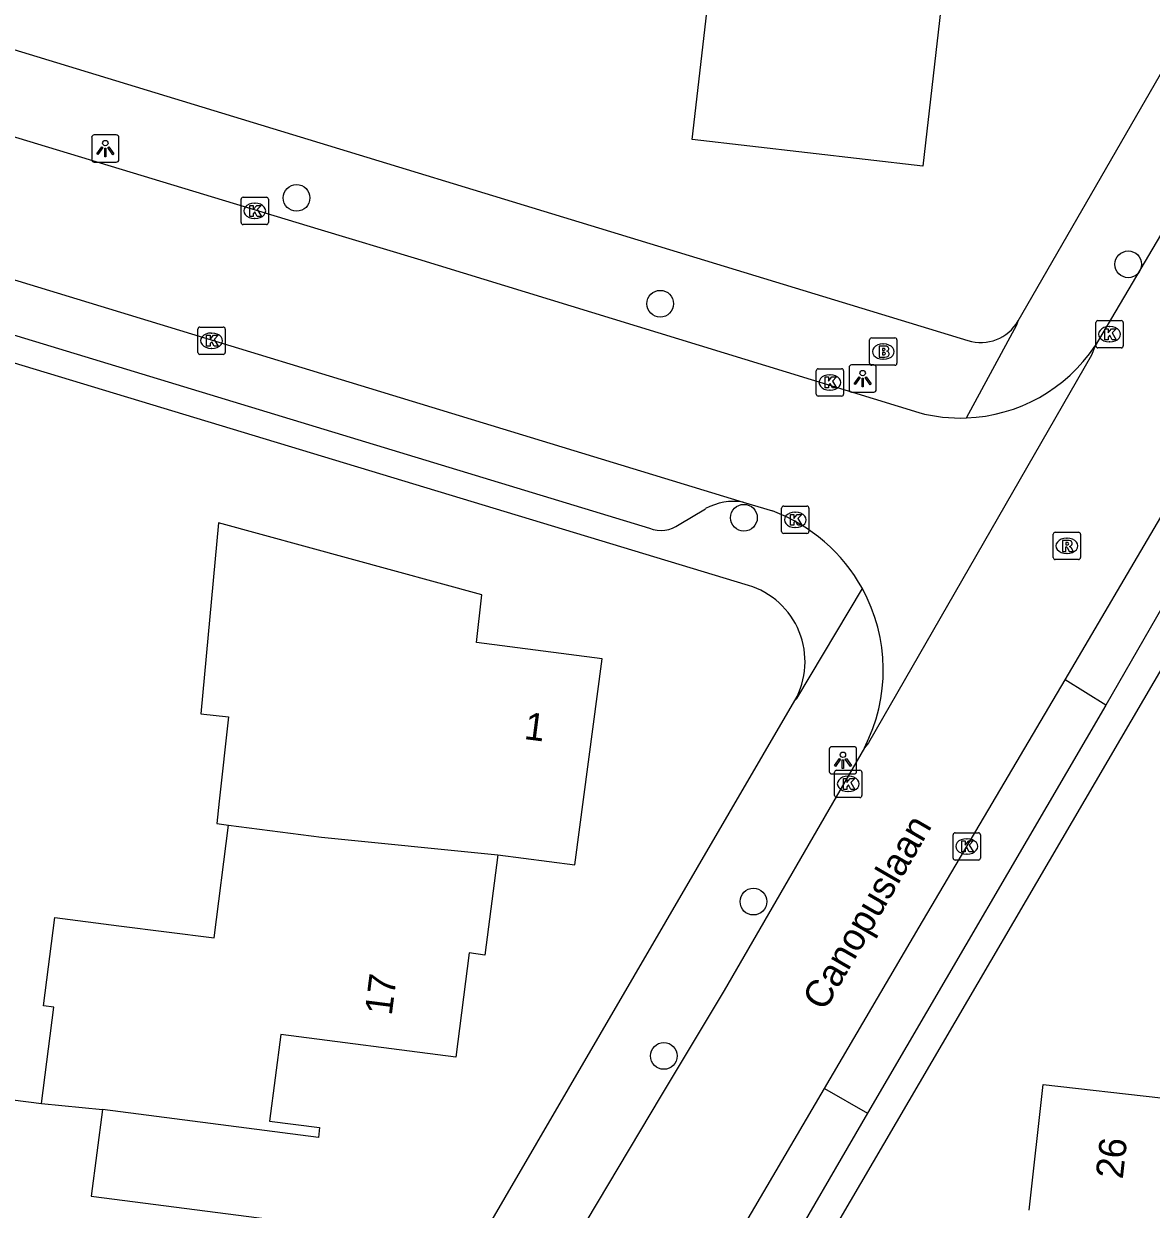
# Model space of a CAD drawing. Extents: x 162398 to 163643, y 386453 to 387397.
# Drawn here: x 162852.66 to 162893.95, y 386684.22 to 386727.63 of the extents above; entities that cross this region are included whole.
import ezdxf

# ---------------------------------------------------------------- set-up
doc = ezdxf.new("R2010")
doc.units = 0
for name, color, linetype in [('IMGEO_Boom', 7, 'Continuous'), ('IMGEO_Brandkraan', 7, 'Continuous'), ('IMGEO_Kolk', 7, 'Continuous'), ('IMGEO_Lichtpunt', 7, 'Continuous'), ('IMGEO_Openbare_ruimte_label', 7, 'Continuous'), ('IMGEO_Pand', 7, 'Continuous'), ('IMGEO_Pand_nummerreeks', 7, 'Continuous'), ('IMGEO_Rijbaan_lokaal_open', 7, 'Continuous'), ('IMGEO_Rioolput', 7, 'Continuous'), ('IMGEO_Voetpad_open', 7, 'Continuous')]:
    doc.layers.add(name, color=color, linetype=linetype)

msp = doc.modelspace()

# ---------------------------------------------------------------- linework, layer by layer
at = {"layer": 'IMGEO_Boom'}
for centre in [(162862.649, 386721.249), (162893.101, 386718.817), (162875.964, 386717.375), (162879.029, 386709.541), (162879.377, 386695.487), (162876.097, 386689.837)]:
    msp.add_circle(centre, 0.489, dxfattribs=at)
at = {"layer": 'IMGEO_Brandkraan'}
for p, q in [((162883.632, 386715.196), (162883.632, 386716.048)), ((162883.707, 386716.122), (162884.559, 386716.122)), ((162884.633, 386716.048), (162884.633, 386715.196)), ((162884.12, 386715.902), (162884.145, 386715.902)), ((162884.143, 386715.342), (162884.118, 386715.342)), ((162884.559, 386715.122), (162883.707, 386715.122))]:
    msp.add_line(p, q, dxfattribs=at)
for points in [[(162883.632, 386715.196), (162883.632, 386716.048)], [(162883.707, 386716.122), (162884.559, 386716.122)], [(162884.633, 386716.048), (162884.633, 386715.196)], [(162883.98, 386715.822), (162883.98, 386715.422), (162884.193, 386715.422)], [(162884.211, 386715.822), (162883.98, 386715.822)], [(162884.159, 386715.741), (162884.105, 386715.741), (162884.105, 386715.665)], [(162884.105, 386715.665), (162884.158, 386715.665)], [(162884.167, 386715.589), (162884.105, 386715.589), (162884.105, 386715.508)], [(162884.105, 386715.508), (162884.167, 386715.508)], [(162884.559, 386715.122), (162883.707, 386715.122)]]:
    msp.add_lwpolyline(points, dxfattribs=at)
for centre, radius, start, end in [((162883.709, 386716.046), 0.0765, 91.552, 178.448), ((162883.709, 386716.046), 0.0765, 91.552, 178.448), ((162884.557, 386716.046), 0.0765, 1.552, 88.448), ((162884.557, 386716.046), 0.0765, 1.552, 88.448), ((162884.16, 386715.703), 0.0379, 267.8285, 90.9355), ((162884.215, 386715.677), 0.145, 59.4692, 91.5367), ((162884.24, 386715.724), 0.0922, 285.5137, 58.1501), ((162884.245, 386715.532), 0.105, 301.3115, 78.989), ((162883.709, 386715.198), 0.0765, 181.552, 268.448), ((162883.709, 386715.198), 0.0765, 181.552, 268.448), ((162884.168, 386715.548), 0.0404, 269.8759, 90.5077), ((162884.199, 386715.673), 0.251, 268.6676, 293.5347), ((162884.557, 386715.198), 0.0765, 271.552, 358.448), ((162884.557, 386715.198), 0.0765, 271.552, 358.448)]:
    msp.add_arc(centre, radius, start, end, dxfattribs=at)
for centre, major_axis, ratio, start_param, end_param in [((162884.119, 386715.622), (-0.387, 0.002), 0.722429, 4.712389, 7.853982), ((162884.144, 386715.622), (-0.39, 0.002), 0.717154, 1.570796, 4.712389)]:
    msp.add_ellipse(centre, major_axis=major_axis, ratio=ratio, start_param=start_param, end_param=end_param, dxfattribs=at)
at = {"layer": 'IMGEO_Kolk'}
for p, q in [((162860.691, 386721.273), (162861.543, 386721.273)), ((162860.616, 386720.347), (162860.616, 386721.199)), ((162861.104, 386721.053), (162861.129, 386721.053)), ((162861.617, 386721.199), (162861.617, 386720.347)), ((162861.127, 386720.493), (162861.102, 386720.493)), ((162861.543, 386720.273), (162860.691, 386720.273)), ((162859.111, 386716.521), (162859.963, 386716.521)), ((162891.917, 386715.831), (162891.917, 386716.683)), ((162891.992, 386716.757), (162892.844, 386716.757)), ((162892.405, 386716.537), (162892.43, 386716.537)), ((162892.918, 386716.683), (162892.918, 386715.831)), ((162859.036, 386715.595), (162859.036, 386716.447)), ((162859.524, 386716.301), (162859.549, 386716.301)), ((162860.037, 386716.447), (162860.037, 386715.595)), ((162859.547, 386715.741), (162859.522, 386715.741)), ((162892.844, 386715.757), (162891.992, 386715.757)), ((162892.428, 386715.977), (162892.403, 386715.977)), ((162859.963, 386715.521), (162859.111, 386715.521)), ((162881.678, 386714.067), (162881.678, 386714.919)), ((162881.753, 386714.993), (162882.605, 386714.993)), ((162882.166, 386714.773), (162882.191, 386714.773)), ((162882.679, 386714.919), (162882.679, 386714.067)), ((162882.605, 386713.993), (162881.753, 386713.993)), ((162882.189, 386714.213), (162882.164, 386714.213)), ((162880.485, 386709.964), (162881.337, 386709.964)), ((162880.41, 386709.038), (162880.41, 386709.89)), ((162880.898, 386709.744), (162880.923, 386709.744)), ((162881.411, 386709.89), (162881.411, 386709.038)), ((162880.921, 386709.184), (162880.896, 386709.184)), ((162881.337, 386708.964), (162880.485, 386708.964)), ((162882.349, 386699.371), (162882.349, 386700.223)), ((162882.424, 386700.297), (162883.276, 386700.297)), ((162882.837, 386700.077), (162882.862, 386700.077)), ((162883.35, 386700.223), (162883.35, 386699.371)), ((162883.276, 386699.297), (162882.424, 386699.297)), ((162882.86, 386699.517), (162882.835, 386699.517)), ((162886.689, 386697.082), (162886.689, 386697.934)), ((162886.764, 386698.008), (162887.616, 386698.008)), ((162887.69, 386697.934), (162887.69, 386697.082)), ((162887.177, 386697.788), (162887.202, 386697.788)), ((162887.616, 386697.008), (162886.764, 386697.008)), ((162887.2, 386697.228), (162887.175, 386697.228))]:
    msp.add_line(p, q, dxfattribs=at)
for points in [[(162860.691, 386721.273), (162861.543, 386721.273)], [(162860.616, 386720.347), (162860.616, 386721.199)], [(162860.937, 386720.973), (162861.06, 386720.973), (162861.06, 386720.822), (162861.19, 386720.973), (162861.354, 386720.973), (162861.208, 386720.822), (162861.361, 386720.573), (162861.209, 386720.573), (162861.124, 386720.737), (162861.06, 386720.67), (162861.06, 386720.573), (162860.937, 386720.573), (162860.937, 386720.973)], [(162861.617, 386721.199), (162861.617, 386720.347)], [(162861.543, 386720.273), (162860.691, 386720.273)], [(162859.111, 386716.521), (162859.963, 386716.521)], [(162891.917, 386715.831), (162891.917, 386716.683)], [(162891.992, 386716.757), (162892.844, 386716.757)], [(162892.918, 386716.683), (162892.918, 386715.831)], [(162859.036, 386715.595), (162859.036, 386716.447)], [(162859.357, 386716.221), (162859.48, 386716.221), (162859.48, 386716.07), (162859.61, 386716.221), (162859.774, 386716.221), (162859.628, 386716.07), (162859.781, 386715.821), (162859.629, 386715.821), (162859.544, 386715.985), (162859.48, 386715.918), (162859.48, 386715.821), (162859.357, 386715.821), (162859.357, 386716.221)], [(162860.037, 386716.447), (162860.037, 386715.595)], [(162892.238, 386716.457), (162892.361, 386716.457), (162892.361, 386716.306), (162892.491, 386716.457), (162892.655, 386716.457), (162892.509, 386716.306), (162892.662, 386716.057), (162892.51, 386716.057), (162892.425, 386716.221), (162892.361, 386716.154), (162892.361, 386716.057), (162892.238, 386716.057), (162892.238, 386716.457)], [(162892.844, 386715.757), (162891.992, 386715.757)], [(162859.963, 386715.521), (162859.111, 386715.521)], [(162881.678, 386714.067), (162881.678, 386714.919)], [(162881.753, 386714.993), (162882.605, 386714.993)], [(162882.679, 386714.919), (162882.679, 386714.067)], [(162881.999, 386714.693), (162882.122, 386714.693), (162882.122, 386714.542), (162882.252, 386714.693), (162882.416, 386714.693), (162882.27, 386714.542), (162882.423, 386714.293), (162882.271, 386714.293), (162882.186, 386714.457), (162882.122, 386714.39), (162882.122, 386714.293), (162881.999, 386714.293), (162881.999, 386714.693)], [(162882.605, 386713.993), (162881.753, 386713.993)], [(162880.485, 386709.964), (162881.337, 386709.964)], [(162880.41, 386709.038), (162880.41, 386709.89)], [(162880.731, 386709.664), (162880.854, 386709.664), (162880.854, 386709.513), (162880.984, 386709.664), (162881.148, 386709.664), (162881.002, 386709.513), (162881.155, 386709.264), (162881.003, 386709.264), (162880.918, 386709.428), (162880.854, 386709.361), (162880.854, 386709.264), (162880.731, 386709.264), (162880.731, 386709.664)], [(162881.411, 386709.89), (162881.411, 386709.038)], [(162881.337, 386708.964), (162880.485, 386708.964)], [(162882.349, 386699.371), (162882.349, 386700.223)], [(162882.424, 386700.297), (162883.276, 386700.297)], [(162882.67, 386699.997), (162882.793, 386699.997), (162882.793, 386699.846), (162882.923, 386699.997), (162883.087, 386699.997), (162882.941, 386699.846), (162883.094, 386699.597), (162882.942, 386699.597), (162882.857, 386699.761), (162882.793, 386699.694), (162882.793, 386699.597), (162882.67, 386699.597), (162882.67, 386699.997)], [(162883.35, 386700.223), (162883.35, 386699.371)], [(162883.276, 386699.297), (162882.424, 386699.297)], [(162886.689, 386697.082), (162886.689, 386697.934)], [(162886.764, 386698.008), (162887.616, 386698.008)], [(162887.69, 386697.934), (162887.69, 386697.082)], [(162887.01, 386697.708), (162887.133, 386697.708), (162887.133, 386697.557), (162887.263, 386697.708), (162887.427, 386697.708), (162887.281, 386697.557), (162887.434, 386697.308), (162887.282, 386697.308), (162887.197, 386697.472), (162887.133, 386697.405), (162887.133, 386697.308), (162887.01, 386697.308), (162887.01, 386697.708)], [(162887.616, 386697.008), (162886.764, 386697.008)]]:
    msp.add_lwpolyline(points, dxfattribs=at)
for centre, start, end in [((162860.693, 386721.197), 91.552, 178.448), ((162860.693, 386721.197), 91.552, 178.448), ((162861.541, 386721.197), 1.552, 88.448), ((162861.541, 386721.197), 1.552, 88.448), ((162860.693, 386720.349), 181.552, 268.448), ((162860.693, 386720.349), 181.552, 268.448), ((162861.541, 386720.349), 271.552, 358.448), ((162861.541, 386720.349), 271.552, 358.448), ((162859.113, 386716.445), 91.552, 178.448), ((162859.113, 386716.445), 91.552, 178.448), ((162859.961, 386716.445), 1.552, 88.448), ((162859.961, 386716.445), 1.552, 88.448), ((162891.994, 386716.681), 91.552, 178.448), ((162891.994, 386716.681), 91.552, 178.448), ((162892.842, 386716.681), 1.552, 88.448), ((162892.842, 386716.681), 1.552, 88.448), ((162891.994, 386715.833), 181.552, 268.448), ((162891.994, 386715.833), 181.552, 268.448), ((162892.842, 386715.833), 271.552, 358.448), ((162892.842, 386715.833), 271.552, 358.448), ((162859.113, 386715.597), 181.552, 268.448), ((162859.113, 386715.597), 181.552, 268.448), ((162859.961, 386715.597), 271.552, 358.448), ((162859.961, 386715.597), 271.552, 358.448), ((162881.755, 386714.917), 91.552, 178.448), ((162881.755, 386714.917), 91.552, 178.448), ((162882.603, 386714.917), 1.552, 88.448), ((162882.603, 386714.917), 1.552, 88.448), ((162881.755, 386714.069), 181.552, 268.448), ((162881.755, 386714.069), 181.552, 268.448), ((162882.603, 386714.069), 271.552, 358.448), ((162882.603, 386714.069), 271.552, 358.448), ((162880.487, 386709.888), 91.552, 178.448), ((162880.487, 386709.888), 91.552, 178.448), ((162881.335, 386709.888), 1.552, 88.448), ((162881.335, 386709.888), 1.552, 88.448), ((162880.487, 386709.04), 181.552, 268.448), ((162880.487, 386709.04), 181.552, 268.448), ((162881.335, 386709.04), 271.552, 358.448), ((162881.335, 386709.04), 271.552, 358.448), ((162882.426, 386700.221), 91.552, 178.448), ((162882.426, 386700.221), 91.552, 178.448), ((162883.274, 386700.221), 1.552, 88.448), ((162883.274, 386700.221), 1.552, 88.448), ((162882.426, 386699.373), 181.552, 268.448), ((162882.426, 386699.373), 181.552, 268.448), ((162883.274, 386699.373), 271.552, 358.448), ((162883.274, 386699.373), 271.552, 358.448), ((162886.766, 386697.932), 91.552, 178.448), ((162886.766, 386697.932), 91.552, 178.448), ((162887.614, 386697.932), 1.552, 88.448), ((162887.614, 386697.932), 1.552, 88.448), ((162886.766, 386697.084), 181.552, 268.448), ((162886.766, 386697.084), 181.552, 268.448), ((162887.614, 386697.084), 271.552, 358.448), ((162887.614, 386697.084), 271.552, 358.448)]:
    msp.add_arc(centre, 0.0765, start, end, dxfattribs=at)
for centre, major_axis, ratio, start_param, end_param in [((162861.103, 386720.773), (-0.387, 0.002), 0.722429, 4.712389, 7.853982), ((162861.128, 386720.773), (-0.39, 0.002), 0.717154, 1.570796, 4.712389), ((162892.404, 386716.257), (-0.387, 0.002), 0.722429, 4.712389, 7.853982), ((162892.429, 386716.257), (-0.39, 0.002), 0.717154, 1.570796, 4.712389), ((162859.523, 386716.021), (-0.387, 0.002), 0.722429, 4.712389, 7.853982), ((162859.548, 386716.021), (-0.39, 0.002), 0.717154, 1.570796, 4.712389), ((162882.165, 386714.493), (-0.387, 0.002), 0.722429, 4.712389, 7.853982), ((162882.19, 386714.493), (-0.39, 0.002), 0.717154, 1.570796, 4.712389), ((162880.897, 386709.464), (-0.387, 0.002), 0.722429, 4.712389, 7.853982), ((162880.922, 386709.464), (-0.39, 0.002), 0.717154, 1.570796, 4.712389), ((162882.836, 386699.797), (-0.387, 0.002), 0.722429, 4.712389, 7.853982), ((162882.861, 386699.797), (-0.39, 0.002), 0.717154, 1.570796, 4.712389), ((162887.176, 386697.508), (-0.387, 0.002), 0.722429, 4.712389, 7.853982), ((162887.201, 386697.508), (-0.39, 0.002), 0.717154, 1.570796, 4.712389)]:
    msp.add_ellipse(centre, major_axis=major_axis, ratio=ratio, start_param=start_param, end_param=end_param, dxfattribs=at)
at = {"layer": 'IMGEO_Lichtpunt'}
for p, q in [((162855.147, 386723.458), (162855.147, 386722.651)), ((162855.147, 386723.458), (162855.147, 386722.651)), ((162856.049, 386723.553), (162855.241, 386723.553)), ((162856.049, 386723.553), (162855.241, 386723.553)), ((162856.143, 386722.651), (162856.143, 386723.458)), ((162856.143, 386722.651), (162856.143, 386723.458)), ((162855.241, 386722.557), (162856.049, 386722.557)), ((162855.241, 386722.557), (162856.049, 386722.557)), ((162882.878, 386715.038), (162882.878, 386714.231)), ((162882.878, 386715.038), (162882.878, 386714.231)), ((162883.78, 386715.133), (162882.972, 386715.133)), ((162883.78, 386715.133), (162882.972, 386715.133)), ((162883.874, 386714.231), (162883.874, 386715.038)), ((162883.874, 386714.231), (162883.874, 386715.038)), ((162882.972, 386714.137), (162883.78, 386714.137)), ((162882.972, 386714.137), (162883.78, 386714.137)), ((162882.156, 386701.063), (162882.156, 386700.256)), ((162882.156, 386701.063), (162882.156, 386700.256)), ((162883.058, 386701.158), (162882.25, 386701.158)), ((162883.058, 386701.158), (162882.25, 386701.158)), ((162883.152, 386700.256), (162883.152, 386701.063)), ((162883.152, 386700.256), (162883.152, 386701.063)), ((162882.25, 386700.162), (162883.058, 386700.162)), ((162882.25, 386700.162), (162883.058, 386700.162))]:
    msp.add_line(p, q, dxfattribs=at)
for points in [[(162855.521, 386723.122), (162855.56, 386723.094), (162855.372, 386722.832), (162855.334, 386722.859), (162855.521, 386723.122)], [(162855.623, 386723.074), (162855.67, 386723.074), (162855.67, 386722.752), (162855.623, 386722.752), (162855.623, 386723.074)], [(162855.733, 386723.094), (162855.771, 386723.121), (162855.958, 386722.859), (162855.919, 386722.831), (162855.733, 386723.094)], [(162883.252, 386714.702), (162883.291, 386714.674), (162883.103, 386714.412), (162883.065, 386714.439), (162883.252, 386714.702)], [(162883.354, 386714.654), (162883.401, 386714.654), (162883.401, 386714.332), (162883.354, 386714.332), (162883.354, 386714.654)], [(162883.464, 386714.674), (162883.502, 386714.701), (162883.689, 386714.439), (162883.65, 386714.411), (162883.464, 386714.674)], [(162882.53, 386700.727), (162882.569, 386700.699), (162882.381, 386700.437), (162882.343, 386700.464), (162882.53, 386700.727)], [(162882.632, 386700.679), (162882.679, 386700.679), (162882.679, 386700.357), (162882.632, 386700.357), (162882.632, 386700.679)], [(162882.742, 386700.699), (162882.78, 386700.726), (162882.967, 386700.464), (162882.928, 386700.436), (162882.742, 386700.699)]]:
    msp.add_lwpolyline(points, dxfattribs=at)
for centre in [(162855.646, 386723.256), (162883.377, 386714.836), (162882.655, 386700.861)]:
    msp.add_circle(centre, 0.0994, dxfattribs=at)
for centre, start, end in [((162855.241, 386723.458), 90, 180), ((162855.241, 386723.458), 90, 180), ((162856.049, 386723.458), 0, 90), ((162856.049, 386723.458), 0, 90), ((162855.241, 386722.651), 180, 270), ((162855.241, 386722.651), 180, 270), ((162856.049, 386722.651), 270, 0), ((162856.049, 386722.651), 270, 360), ((162882.972, 386715.038), 90, 180), ((162882.972, 386715.038), 90, 180), ((162883.78, 386715.038), 0, 90), ((162883.78, 386715.038), 0, 90), ((162882.972, 386714.231), 180, 270), ((162882.972, 386714.231), 180, 270), ((162883.78, 386714.231), 270, 0), ((162883.78, 386714.231), 270, 360), ((162882.25, 386701.063), 90, 180), ((162882.25, 386701.063), 90, 180), ((162883.058, 386701.063), 0, 90), ((162883.058, 386701.063), 0, 90), ((162882.25, 386700.256), 180, 270), ((162882.25, 386700.256), 180, 270), ((162883.058, 386700.256), 270, 0), ((162883.058, 386700.256), 270, 360)]:
    msp.add_arc(centre, 0.0946, start, end, dxfattribs=at)
at = {"layer": 'IMGEO_Pand'}
for points in [[(162883.57, 386735.874), (162885.555, 386735.646), (162890.522, 386735.076), (162889.736, 386728.216), (162886.289, 386728.612), (162885.578, 386722.413), (162877.133, 386723.382), (162877.703, 386728.35), (162878.213, 386732.8), (162884.39, 386732.092), (162884.768, 386735.388), (162883.531, 386735.53), (162883.57, 386735.874)], [(162870.016, 386697.195), (162872.835, 386696.833), (162873.835, 386704.376), (162869.232, 386704.973), (162869.427, 386706.713), (162859.795, 386709.352), (162859.138, 386702.363), (162860.155, 386702.252), (162859.818, 386699.163), (162859.729, 386698.343), (162860.155, 386698.288)], [(162853.314, 386688.091), (162853.766, 386691.62), (162853.387, 386691.668), (162853.803, 386694.906), (162856.147, 386694.606), (162859.626, 386694.16), (162860.155, 386698.288)], [(162860.155, 386698.288), (162863.557, 386697.851), (162870.016, 386697.195)], [(162870.016, 386697.195), (162869.546, 386693.532), (162868.969, 386693.606), (162868.48, 386689.794), (162862.068, 386690.617), (162861.662, 386687.451), (162863.494, 386687.216), (162863.448, 386686.856), (162855.537, 386687.872)], [(162889.475, 386684.194), (162889.986, 386688.788), (162894.3, 386688.308), (162895.015, 386694.741), (162896.789, 386694.543)], [(162851.227, 386677.315), (162851.732, 386681.252), (162848.215, 386681.704), (162849.104, 386688.632), (162853.314, 386688.091)], [(162853.314, 386688.091), (162855.537, 386687.872)], [(162855.537, 386687.872), (162855.13, 386684.7), (162861.661, 386683.862), (162860.666, 386676.106), (162857.797, 386676.475)]]:
    msp.add_lwpolyline(points, dxfattribs=at)
at = {"layer": 'IMGEO_Rijbaan_lokaal_open'}
for points in [[(162924.748, 386772.326), (162923.585, 386770.172), (162916.906, 386758.651), (162914.448, 386754.399), (162902.012, 386732.978), (162899.696, 386729.077), (162891.884, 386715.828)], [(162781.987, 386751.424), (162782.216, 386751.254), (162782.452, 386751.096), (162784.174, 386750), (162791.551, 386745.306), (162799.553, 386740.722), (162800.806, 386740.18), (162804.196, 386738.713), (162807.535, 386737.268), (162816.968, 386734.216), (162820.57, 386733.086), (162832.38, 386729.513), (162836.03, 386728.409), (162847.632, 386724.899), (162851.256, 386723.803), (162863.426, 386720.121), (162867.077, 386719.017), (162885.432, 386713.389)], [(162845.069, 386720.455), (162879.001, 386710.115)], [(162891.884, 386715.828), (162891.751, 386715.492), (162883.587, 386701.299), (162883.441, 386701.116)], [(162879.001, 386710.115), (162880.077, 386709.787)], [(162890.79, 386703.612), (162894.3, 386709.561)], [(162895.758, 386708.719), (162892.276, 386702.679)], [(162881.985, 386688.65), (162885.442, 386694.548), (162890.79, 386703.612)], [(162892.276, 386702.679), (162890.79, 386703.612)], [(162883.441, 386701.116), (162878.304, 386692.227), (162875.997, 386688.39), (162872.488, 386682.498), (162864.182, 386668.166), (162861.776, 386664.024), (162861.182, 386662.993)], [(162878.653, 386682.966), (162881.985, 386688.65)], [(162881.985, 386688.65), (162883.554, 386687.748)], [(162883.554, 386687.748), (162880.224, 386682.009)]]:
    msp.add_lwpolyline(points, dxfattribs=at)
for centre, radius, start, end in [((162886.953, 386719.12), 5.929, 272.1372, 326.2752), ((162886.95, 386719.098), 5.907, 255.113, 272.1777), ((162877.914, 386703.956), 6.219, 28.7239, 69.6504), ((162877.911, 386703.962), 6.219, 332.7707, 28.6644)]:
    msp.add_arc(centre, radius, start, end, dxfattribs=at)
at = {"layer": 'IMGEO_Rioolput'}
for p, q in [((162890.353, 386708.084), (162890.353, 386708.936)), ((162890.428, 386709.01), (162891.28, 386709.01)), ((162890.841, 386708.79), (162890.866, 386708.79)), ((162891.354, 386708.936), (162891.354, 386708.084)), ((162890.864, 386708.23), (162890.839, 386708.23)), ((162891.28, 386708.01), (162890.428, 386708.01))]:
    msp.add_line(p, q, dxfattribs=at)
for points in [[(162890.353, 386708.084), (162890.353, 386708.936)], [(162890.428, 386709.01), (162891.28, 386709.01)], [(162890.942, 386708.708), (162890.69, 386708.71), (162890.69, 386708.31)], [(162891.354, 386708.936), (162891.354, 386708.084)], [(162890.69, 386708.31), (162890.814, 386708.31), (162890.814, 386708.472), (162890.825, 386708.472)], [(162890.868, 386708.629), (162890.814, 386708.629), (162890.814, 386708.548)], [(162890.814, 386708.548), (162890.866, 386708.548)], [(162890.872, 386708.443), (162890.943, 386708.31), (162891.083, 386708.31), (162891.018, 386708.436)], [(162891.28, 386708.01), (162890.428, 386708.01)]]:
    msp.add_lwpolyline(points, dxfattribs=at)
for centre, radius, start, end in [((162890.43, 386708.934), 0.0765, 91.552, 178.448), ((162890.43, 386708.934), 0.0765, 91.552, 178.448), ((162890.941, 386708.598), 0.109, 350.3612, 89.416), ((162891.278, 386708.934), 0.0765, 1.552, 88.448), ((162891.278, 386708.934), 0.0765, 1.552, 88.448), ((162890.824, 386708.419), 0.0533, 26.0293, 88.6989), ((162890.85, 386708.737), 0.19, 274.7715, 282.9687), ((162890.874, 386708.533), 0.0964, 77.0061, 93.1865), ((162890.888, 386708.59), 0.0378, 276.6634, 79.6772), ((162890.939, 386708.598), 0.112, 277.5842, 350.9817), ((162890.923, 386708.383), 0.108, 29.5134, 73.7905), ((162890.43, 386708.086), 0.0765, 181.552, 268.448), ((162890.43, 386708.086), 0.0765, 181.552, 268.448), ((162891.278, 386708.086), 0.0765, 271.552, 358.448), ((162891.278, 386708.086), 0.0765, 271.552, 358.448)]:
    msp.add_arc(centre, radius, start, end, dxfattribs=at)
for centre, major_axis, ratio, start_param, end_param in [((162890.84, 386708.51), (-0.387, 0.002), 0.722429, 4.712389, 7.853982), ((162890.865, 386708.51), (-0.39, 0.002), 0.717154, 1.570796, 4.712389)]:
    msp.add_ellipse(centre, major_axis=major_axis, ratio=ratio, start_param=start_param, end_param=end_param, dxfattribs=at)
at = {"layer": 'IMGEO_Voetpad_open'}
for points in [[(162889.067, 386716.747), (162900.547, 386736.644), (162908.437, 386750), (162912.129, 386756.249)], [(162784.935, 386753.194), (162789.995, 386750), (162795.943, 386746.246), (162800.923, 386743.431), (162807.171, 386740.595), (162809.276, 386739.81), (162887.231, 386716.025)], [(162921.361, 386750.255), (162921.212, 386750), (162863.497, 386651.323), (162799.834, 386651.914)], [(162879.195, 386707.065), (162808.069, 386728.604), (162800.69, 386731.432), (162797.61, 386732.851), (162791.569, 386736.058), (162786.318, 386739.251), (162778.985, 386744.019)], [(162844.481, 386718.603), (162875.573, 386709.156)], [(162887.174, 386713.195), (162889.021, 386716.602), (162889.067, 386716.747)], [(162876.662, 386709.294), (162877.624, 386709.872)], [(162880.898, 386702.85), (162880.963, 386702.928), (162883.368, 386706.945)], [(162858.436, 386664.327), (162880.898, 386702.85)], [(162892.276, 386702.679), (162883.554, 386687.748)]]:
    msp.add_lwpolyline(points, dxfattribs=at)
for centre, radius, start, end in [((162887.699, 386717.529), 1.575, 252.6987, 330.2354), ((162878.675, 386707.938), 2.202, 81.4921, 118.5238), ((162875.994, 386710.199), 1.125, 248.0251, 306.4192), ((162878.351, 386704.272), 2.917, 330.8169, 73.1838)]:
    msp.add_arc(centre, radius, start, end, dxfattribs=at)

# ---------------------------------------------------------------- texts
at = {"layer": 'IMGEO_Openbare_ruimte_label'}
msp.add_text('Canopuslaan', height=1, rotation=59.921, dxfattribs=at).set_placement((162881.985, 386691.444))
at = {"layer": 'IMGEO_Pand_nummerreeks'}
for s, rotation, p in [('1', 352.6088, (162870.951, 386701.443)), ('17', 82.6893, (162866.131, 386691.292)), ('26', 83.653, (162892.899, 386685.307))]:
    msp.add_text(s, height=1, rotation=rotation, dxfattribs=at).set_placement(p)

doc.saveas('drawing.dxf')
